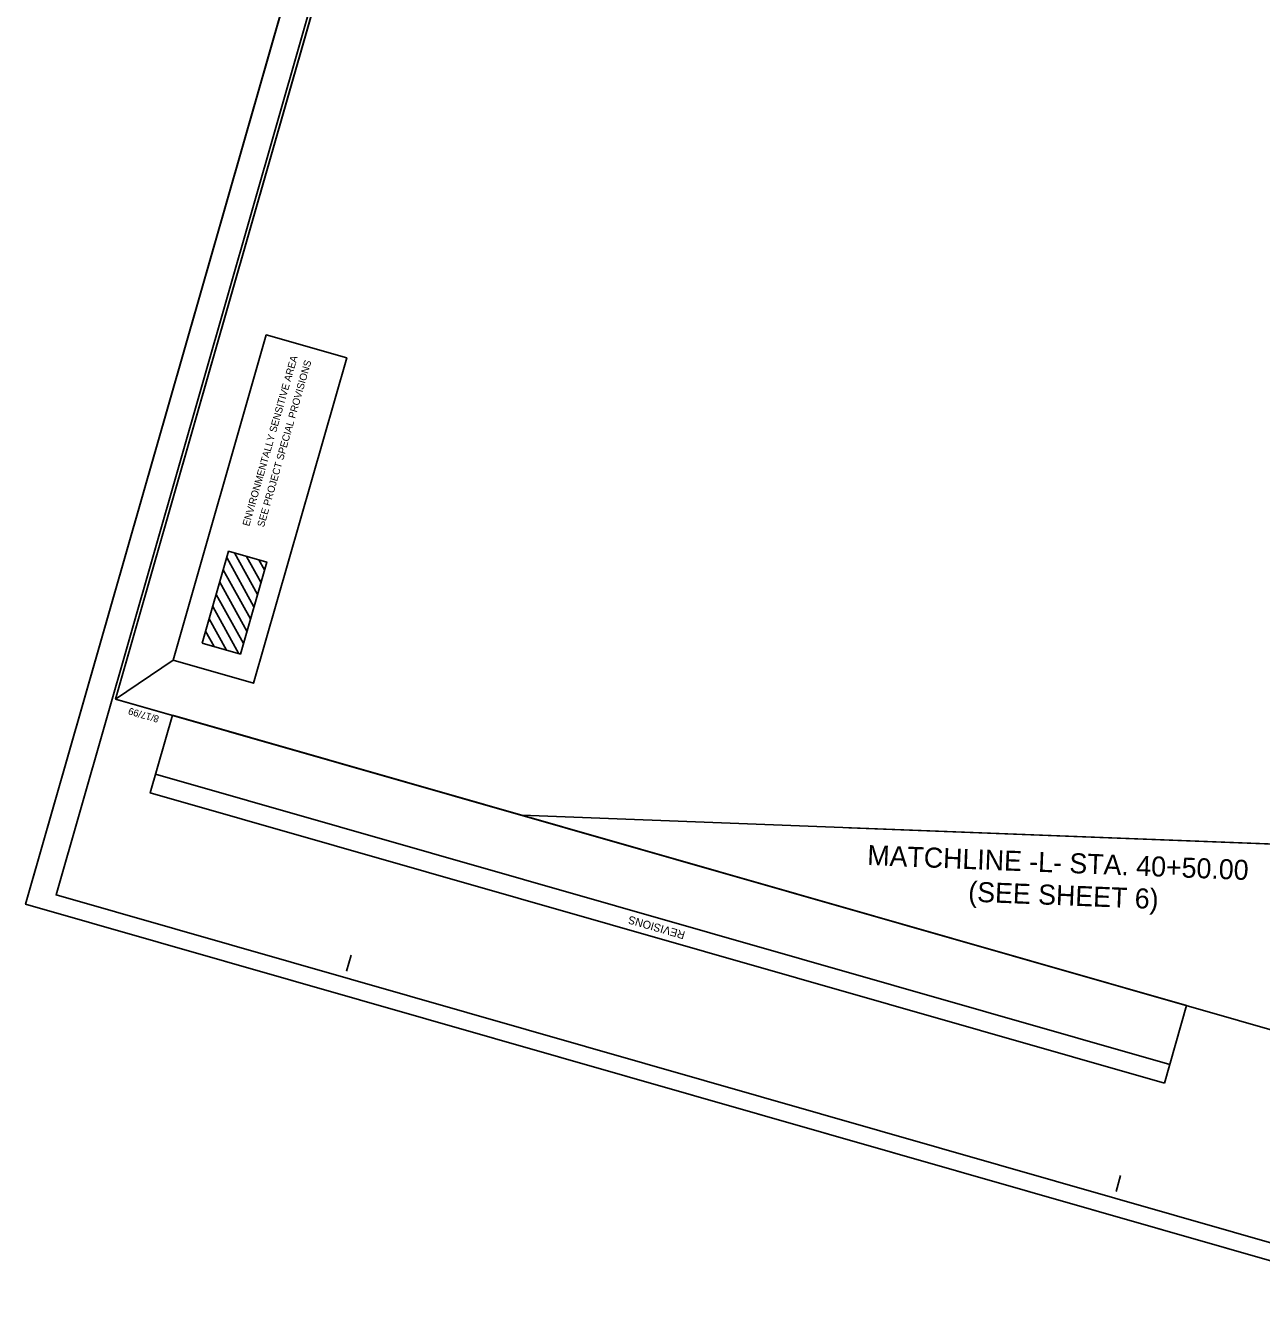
# Model space of a CAD drawing. Extents: x 2096976 to 2098492, y 681809 to 689636.
# Drawn here: x 2096976 to 2097902, y 687716 to 688676 of the extents above; entities that cross this region are included whole.
import ezdxf

# ---------------------------------------------------------------- set-up
doc = ezdxf.new("R2010")
doc.units = 0
for name, color, linetype in [('Default', 7, 'Continuous'), ('Matchline', 7, 'Continuous'), ('Matchline Text', 7, 'Continuous'), ('Scratch_Level_6', 7, 'Continuous'), ('Sheet Block Title CELL', 7, 'Continuous'), ('Sheet Data Field CELL', 7, 'Continuous'), ('Sheet Plan And Profile CELL', 7, 'Continuous'), ('Sheet Plan CELL', 7, 'Continuous'), ('Sheet Plot Border Inside CELL', 7, 'Continuous'), ('Sheet Sticker Exception Certification CELL', 7, 'Continuous')]:
    doc.layers.add(name, color=color, linetype=linetype)

msp = doc.modelspace()

# ---------------------------------------------------------------- linework, layer by layer
at = {"layer": 'Default'}
for p, q in [((2097146.86, 688240.39), (2097126.43, 688277.13)), ((2097149.48, 688249.56), (2097132.19, 688280.72)), ((2097152.1, 688258.72), (2097141.4, 688278.08)), ((2097154.73, 688267.9), (2097150.58, 688275.46)), ((2097144.23, 688231.22), (2097123.81, 688267.95)), ((2097141.61, 688222.04), (2097121.19, 688258.79)), ((2097138.98, 688212.87), (2097118.56, 688249.61)), ((2097135.51, 688205.16), (2097115.93, 688240.44)), ((2097126.29, 688207.8), (2097113.31, 688231.27)), ((2097117.12, 688210.42), (2097110.68, 688222.1))]:
    msp.add_line(p, q, dxfattribs=at)
for points in [[(2097086.27, 688200.25), (2097156.06, 688444.08), (2097216.37, 688426.83), (2097146.62, 688182.98)], [(2097108.08, 688213.01), (2097127.82, 688281.98), (2097156.42, 688273.79), (2097136.68, 688204.83)]]:
    msp.add_lwpolyline(points, close=True, dxfattribs=at)
at = {"layer": 'Matchline Text'}
msp.add_line((2097592.68, 688074.63), (2097942.42, 688061.22), dxfattribs=at)
at = {"layer": 'Scratch_Level_6'}
msp.add_line((2097086.27, 688200.25), (2097043.16, 688171.19), dxfattribs=at)
msp.add_lwpolyline([(2097086.27, 688200.25), (2097156.07, 688444.09), (2097216.37, 688426.83), (2097146.57, 688182.99)], close=True, dxfattribs=at)
at = {"layer": 'Sheet Block Title CELL'}
msp.add_lwpolyline([(2098028.44, 687715.97), (2098491.74, 689334.46), (2097439.02, 689635.81), (2096975.72, 688017.32)], close=True, dxfattribs=at)
at = {"layer": 'Sheet Data Field CELL'}
msp.add_lwpolyline([(2098012.79, 687733.97), (2098471.26, 689335.63), (2097457.01, 689625.98), (2096998.53, 688024.31)], close=True, dxfattribs=at)
at = {"layer": 'Sheet Plan And Profile CELL'}
for p, q in [((2097439.02, 689635.81), (2096975.72, 688017.32)), ((2096975.72, 688017.32), (2098028.44, 687715.97))]:
    msp.add_line(p, q, dxfattribs=at)
at = {"layer": 'Sheet Plan CELL'}
msp.add_line((2097833.26, 687897.19), (2097073.15, 688114.76), dxfattribs=at)
msp.add_lwpolyline([(2097829.28, 687883.2), (2097069.16, 688100.79), (2097085.8, 688158.99), (2097845.92, 687941.4)], close=True, dxfattribs=at)
at = {"layer": 'Sheet Plot Border Inside CELL'}
for points in [[(2098102.1, 688055.1), (2097347.73, 688084.03), (2097043.16, 688171.19), (2097346.07, 689229.4), (2097355.46, 689262.19), (2097400.9, 689420.95), (2097628.1, 689355.93), (2097683.15, 689548.26), (2098465.42, 689324.31)], [(2098102.1, 688055.1), (2097347.73, 688084.03), (2097043.16, 688171.19), (2097345.95, 689228.93), (2097355.46, 689262.19), (2097400.91, 689420.95), (2097628.1, 689355.93), (2097683.15, 689548.26), (2098465.42, 689324.31)]]:
    msp.add_lwpolyline(points, close=True, dxfattribs=at)
at = {"layer": 'Sheet Sticker Exception Certification CELL'}
for p, q in [((2097043.16, 688171.19), (2097043.16, 688171.19)), ((2097216.22, 687967.18), (2097219.64, 687979.22)), ((2097793.05, 687802.09), (2097796.5, 687814.1))]:
    msp.add_line(p, q, dxfattribs=at)
for points in [[(2097455.97, 689613.3), (2097043.16, 688171.19), (2098052.61, 687882.22), (2098465.42, 689324.31)], [(2098052.61, 687882.22), (2097043.17, 688171.15), (2097400.9, 689420.95), (2097545.17, 689379.67), (2097600.23, 689571.98), (2098465.42, 689324.31)]]:
    msp.add_lwpolyline(points, close=True, dxfattribs=at)

# ---------------------------------------------------------------- texts
at = {"layer": 'Default'}
for s, p in [('ENVIRONMENTALLY SENSITIVE AREA', (2097143.31, 688300.3)), ('SEE PROJECT SPECIAL PROVISIONS', (2097154.38, 688299.64))]:
    msp.add_text(s, height=5.4, rotation=74.0315, dxfattribs=at).set_placement(p)
at = {"layer": 'Matchline'}
for s, p in [('MATCHLINE -L- STA. 40+50.00', (2097606.4, 688046.77)), ('(SEE SHEET 6)', (2097682.08, 688019.39))]:
    msp.add_text(s, height=15, rotation=357.73729, dxfattribs=at).set_placement(p)
at = {"layer": 'Sheet Plan CELL'}
msp.add_text('REVISIONS', height=6, rotation=164.02589, dxfattribs=at).set_placement((2097470.52, 687996.81))
at = {"layer": 'Sheet Sticker Exception Certification CELL'}
msp.add_text('8/17/99', height=5.25, rotation=164.02589, dxfattribs=at).set_placement((2097076.14, 688158.39))

doc.saveas('drawing.dxf')
